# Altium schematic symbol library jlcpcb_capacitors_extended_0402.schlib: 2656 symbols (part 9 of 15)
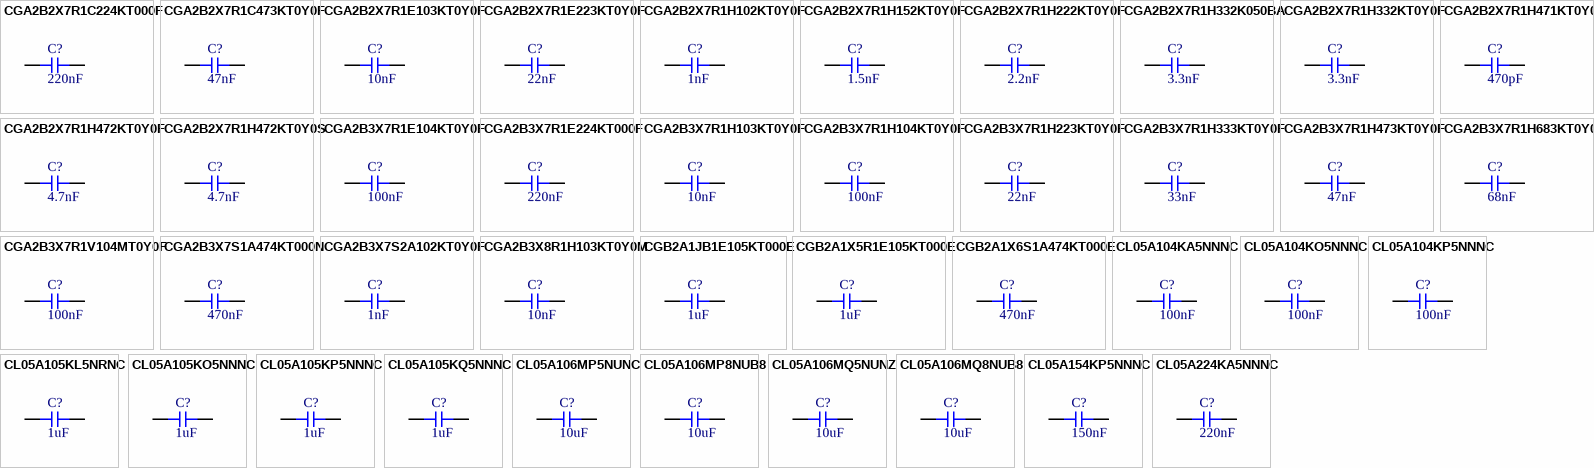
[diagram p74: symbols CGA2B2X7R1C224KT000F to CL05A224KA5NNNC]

## CL05A105KL5NRNC
designator C?  Capacitance: 1uF  (hidden comment: *)
Capacitor, Ceramic (MLCC), 1uF, ±10%, 35V, X5R, ±10%, SMD 0402; Manufacturer: Samsung Electro-Mechanics; Manufacturer Part Number: CL05A105KL5NRNC
footprint CAP-0402 (0402 (1005M) Capacitor)
pins: 1, 2

## CL05A105KO5NNNC
designator C?  Capacitance: 1uF  (hidden comment: *)
Capacitor, Ceramic (MLCC), 1uF, ±10%, 16V, X5R, ±10%, SMD 0402; Manufacturer: Samsung Electro-Mechanics; Manufacturer Part Number: CL05A105KO5NNNC
footprint CAP-0402 (0402 (1005M) Capacitor)
pins: 1, 2

## CL05A105KP5NNNC
designator C?  Capacitance: 1uF  (hidden comment: *)
Capacitor, Ceramic (MLCC), 1uF, ±10%, 10V, X5R, ±10%, SMD 0402; Manufacturer: Samsung Electro-Mechanics; Manufacturer Part Number: CL05A105KP5NNNC
footprint CAP-0402 (0402 (1005M) Capacitor)
pins: 1, 2

## CL05A105KQ5NNNC
designator C?  Capacitance: 1uF  (hidden comment: *)
Capacitor, Ceramic (MLCC), 1uF, ±10%, 6.3V, X5R, ±10%, SMD 0402; Manufacturer: Samsung Electro-Mechanics; Manufacturer Part Number: CL05A105KQ5NNNC
footprint CAP-0402 (0402 (1005M) Capacitor)
pins: 1, 2

## CL05A106MP5NUNC
designator C?  Capacitance: 10uF  (hidden comment: *)
Capacitor, Ceramic (MLCC), 10uF, ±20%, 10V, X5R, ±20%, SMD 0402; Manufacturer: Samsung Electro-Mechanics; Manufacturer Part Number: CL05A106MP5NUNC
footprint CAP-0402 (0402 (1005M) Capacitor)
pins: 1, 2

## CL05A106MP8NUB8
designator C?  Capacitance: 10uF  (hidden comment: *)
Capacitor, Ceramic (MLCC), 10uF, ±20%, 10V, X5R, ±20%, SMD 0402; Manufacturer: Samsung Electro-Mechanics; Manufacturer Part Number: CL05A106MP8NUB8
footprint CAP-0402 (0402 (1005M) Capacitor)
pins: 1, 2

## CL05A106MQ5NUNZ
designator C?  Capacitance: 10uF  (hidden comment: *)
Capacitor, Ceramic (MLCC), 10uF, ±20%, 6.3V, ±20%, SMD 0402; Manufacturer: Samsung Electro-Mechanics; Manufacturer Part Number: CL05A106MQ5NUNZ
footprint CAP-0402 (0402 (1005M) Capacitor)
pins: 1, 2

## CL05A106MQ8NUB8
designator C?  Capacitance: 10uF  (hidden comment: *)
Capacitor, Ceramic (MLCC), 10uF, ±20%, 6.3V, X5R, ±20%, SMD 0402; Manufacturer: Samsung Electro-Mechanics; Manufacturer Part Number: CL05A106MQ8NUB8
footprint CAP-0402 (0402 (1005M) Capacitor)
pins: 1, 2

## CL05A154KP5NNNC
designator C?  Capacitance: 150nF  (hidden comment: *)
Capacitor, Ceramic (MLCC), 150nF, ±10%, 10V, X5R, ±10%, SMD 0402; Manufacturer: Samsung Electro-Mechanics; Manufacturer Part Number: CL05A154KP5NNNC
footprint CAP-0402 (0402 (1005M) Capacitor)
pins: 1, 2

## CL05A224KA5NNNC
designator C?  Capacitance: 220nF  (hidden comment: *)
Capacitor, Ceramic (MLCC), 220nF, ±10%, 25V, X5R, ±10%, SMD 0402; Manufacturer: Samsung Electro-Mechanics; Manufacturer Part Number: CL05A224KA5NNNC
footprint CAP-0402 (0402 (1005M) Capacitor)
pins: 1, 2

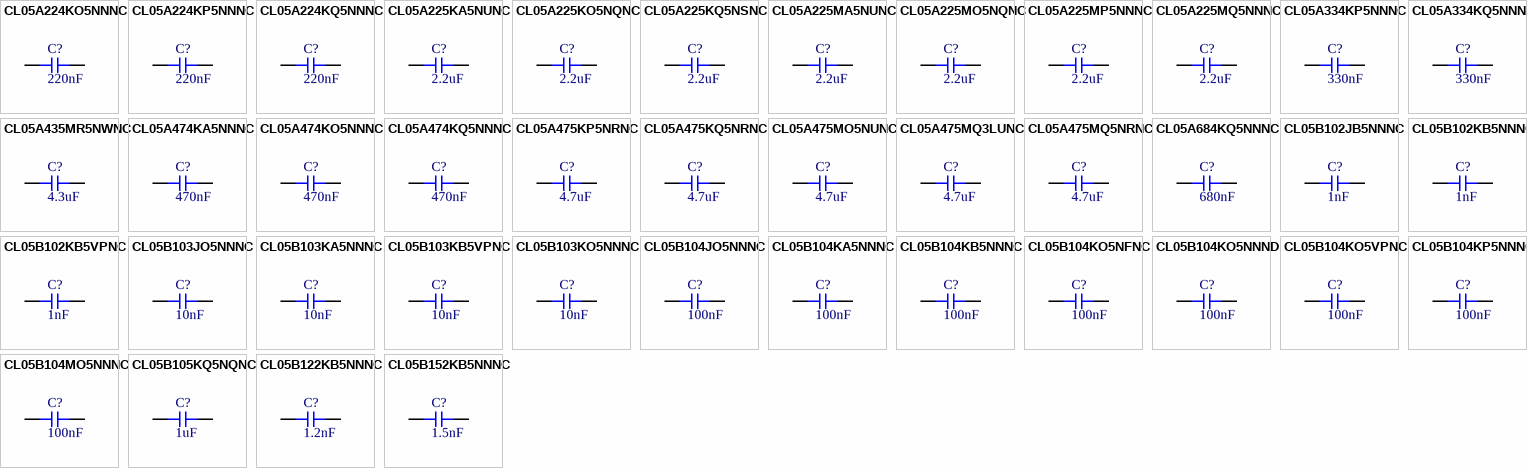
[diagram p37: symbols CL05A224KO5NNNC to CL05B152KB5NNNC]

## CL05A224KO5NNNC
designator C?  Capacitance: 220nF  (hidden comment: *)
Capacitor, Ceramic (MLCC), 220nF, ±10%, 16V, X5R, ±10%, SMD 0402; Manufacturer: Samsung Electro-Mechanics; Manufacturer Part Number: CL05A224KO5NNNC
footprint CAP-0402 (0402 (1005M) Capacitor)
pins: 1, 2

## CL05A224KP5NNNC
designator C?  Capacitance: 220nF  (hidden comment: *)
Capacitor, Ceramic (MLCC), 220nF, ±10%, 10V, X5R, ±10%, SMD 0402; Manufacturer: Samsung Electro-Mechanics; Manufacturer Part Number: CL05A224KP5NNNC
footprint CAP-0402 (0402 (1005M) Capacitor)
pins: 1, 2

## CL05A224KQ5NNNC
designator C?  Capacitance: 220nF  (hidden comment: *)
Capacitor, Ceramic (MLCC), 220nF, ±10%, 6.3V, X5R, ±10%, SMD 0402; Manufacturer: Samsung Electro-Mechanics; Manufacturer Part Number: CL05A224KQ5NNNC
footprint CAP-0402 (0402 (1005M) Capacitor)
pins: 1, 2

## CL05A225KA5NUNC
designator C?  Capacitance: 2.2uF  (hidden comment: *)
Capacitor, Ceramic (MLCC), 2.2uF, ±10%, 25V, X5R, ±10%, SMD 0402; Manufacturer: Samsung Electro-Mechanics; Manufacturer Part Number: CL05A225KA5NUNC
footprint CAP-0402 (0402 (1005M) Capacitor)
pins: 1, 2

## CL05A225KO5NQNC
designator C?  Capacitance: 2.2uF  (hidden comment: *)
Capacitor, Ceramic (MLCC), 2.2uF, ±10%, 16V, X5R, ±10%, SMD 0402; Manufacturer: Samsung Electro-Mechanics; Manufacturer Part Number: CL05A225KO5NQNC
footprint CAP-0402 (0402 (1005M) Capacitor)
pins: 1, 2

## CL05A225KQ5NSNC
designator C?  Capacitance: 2.2uF  (hidden comment: *)
Capacitor, Ceramic (MLCC), 2.2uF, ±10%, 6.3V, X5R, ±10%, SMD 0402; Manufacturer: Samsung Electro-Mechanics; Manufacturer Part Number: CL05A225KQ5NSNC
footprint CAP-0402 (0402 (1005M) Capacitor)
pins: 1, 2

## CL05A225MA5NUNC
designator C?  Capacitance: 2.2uF  (hidden comment: *)
Capacitor, Ceramic (MLCC), 2.2uF, ±20%, 25V, X5R, ±20%, SMD 0402; Manufacturer: Samsung Electro-Mechanics; Manufacturer Part Number: CL05A225MA5NUNC
footprint CAP-0402 (0402 (1005M) Capacitor)
pins: 1, 2

## CL05A225MO5NQNC
designator C?  Capacitance: 2.2uF  (hidden comment: *)
Capacitor, Ceramic (MLCC), 2.2uF, ±20%, 16V, X5R, ±20%, SMD 0402; Manufacturer: Samsung Electro-Mechanics; Manufacturer Part Number: CL05A225MO5NQNC
footprint CAP-0402 (0402 (1005M) Capacitor)
pins: 1, 2

## CL05A225MP5NNNC
designator C?  Capacitance: 2.2uF  (hidden comment: *)
Capacitor, Ceramic (MLCC), 2.2uF, ±20%, 10V, X5R, ±20%, SMD 0402; Manufacturer: Samsung Electro-Mechanics; Manufacturer Part Number: CL05A225MP5NNNC
footprint CAP-0402 (0402 (1005M) Capacitor)
pins: 1, 2

## CL05A225MQ5NNNC
designator C?  Capacitance: 2.2uF  (hidden comment: *)
Capacitor, Ceramic (MLCC), 2.2uF, ±20%, 6.3V, X5R, ±20%, SMD 0402; Manufacturer: Samsung Electro-Mechanics; Manufacturer Part Number: CL05A225MQ5NNNC
footprint CAP-0402 (0402 (1005M) Capacitor)
pins: 1, 2

## CL05A334KP5NNNC
designator C?  Capacitance: 330nF  (hidden comment: *)
Capacitor, Ceramic (MLCC), 330nF, ±10%, 10V, X5R, ±10%, SMD 0402; Manufacturer: Samsung Electro-Mechanics; Manufacturer Part Number: CL05A334KP5NNNC
footprint CAP-0402 (0402 (1005M) Capacitor)
pins: 1, 2

## CL05A334KQ5NNNC
designator C?  Capacitance: 330nF  (hidden comment: *)
Capacitor, Ceramic (MLCC), 330nF, ±10%, 6.3V, X5R, ±10%, SMD 0402; Manufacturer: Samsung Electro-Mechanics; Manufacturer Part Number: CL05A334KQ5NNNC
footprint CAP-0402 (0402 (1005M) Capacitor)
pins: 1, 2

## CL05A435MR5NWNC
designator C?  Capacitance: 4.3uF  (hidden comment: *)
Capacitor, Ceramic (MLCC), 4.3uF, ±20%, 4V, X5R, ±20%, SMD 0402; Manufacturer: Samsung Electro-Mechanics; Manufacturer Part Number: CL05A435MR5NWNC
footprint CAP-0402 (0402 (1005M) Capacitor)
pins: 1, 2

## CL05A474KA5NNNC
designator C?  Capacitance: 470nF  (hidden comment: *)
Capacitor, Ceramic (MLCC), 470nF, ±10%, 25V, X5R, ±10%, SMD 0402; Manufacturer: Samsung Electro-Mechanics; Manufacturer Part Number: CL05A474KA5NNNC
footprint CAP-0402 (0402 (1005M) Capacitor)
pins: 1, 2

## CL05A474KO5NNNC
designator C?  Capacitance: 470nF  (hidden comment: *)
Capacitor, Ceramic (MLCC), 470nF, ±10%, 16V, X5R, ±10%, SMD 0402; Manufacturer: Samsung Electro-Mechanics; Manufacturer Part Number: CL05A474KO5NNNC
footprint CAP-0402 (0402 (1005M) Capacitor)
pins: 1, 2

## CL05A474KQ5NNNC
designator C?  Capacitance: 470nF  (hidden comment: *)
Capacitor, Ceramic (MLCC), 470nF, ±10%, 6.3V, X5R, ±10%, SMD 0402; Manufacturer: Samsung Electro-Mechanics; Manufacturer Part Number: CL05A474KQ5NNNC
footprint CAP-0402 (0402 (1005M) Capacitor)
pins: 1, 2

## CL05A475KP5NRNC
designator C?  Capacitance: 4.7uF  (hidden comment: *)
Capacitor, Ceramic (MLCC), 4.7uF, ±10%, 10V, X5R, ±10%, SMD 0402; Manufacturer: Samsung Electro-Mechanics; Manufacturer Part Number: CL05A475KP5NRNC
footprint CAP-0402 (0402 (1005M) Capacitor)
pins: 1, 2

## CL05A475KQ5NRNC
designator C?  Capacitance: 4.7uF  (hidden comment: *)
Capacitor, Ceramic (MLCC), 4.7uF, ±10%, 6.3V, X5R, ±10%, SMD 0402; Manufacturer: Samsung Electro-Mechanics; Manufacturer Part Number: CL05A475KQ5NRNC
footprint CAP-0402 (0402 (1005M) Capacitor)
pins: 1, 2

## CL05A475MO5NUNC
designator C?  Capacitance: 4.7uF  (hidden comment: *)
Capacitor, Ceramic (MLCC), 4.7uF, ±20%, 16V, X5R, ±20%, SMD 0402; Manufacturer: Samsung Electro-Mechanics; Manufacturer Part Number: CL05A475MO5NUNC
footprint CAP-0402 (0402 (1005M) Capacitor)
pins: 1, 2

## CL05A475MQ3LUNC
designator C?  Capacitance: 4.7uF  (hidden comment: *)
Capacitor, Ceramic (MLCC), 4.7uF, ±20%, 6.3V, X5R, ±20%, SMD 0402; Manufacturer: Samsung Electro-Mechanics; Manufacturer Part Number: CL05A475MQ3LUNC
footprint CAP-0402 (0402 (1005M) Capacitor)
pins: 1, 2

## CL05A475MQ5NRNC
designator C?  Capacitance: 4.7uF  (hidden comment: *)
Capacitor, Ceramic (MLCC), 4.7uF, ±20%, 6.3V, X5R, ±20%, SMD 0402; Manufacturer: Samsung Electro-Mechanics; Manufacturer Part Number: CL05A475MQ5NRNC
footprint CAP-0402 (0402 (1005M) Capacitor)
pins: 1, 2

## CL05A684KQ5NNNC
designator C?  Capacitance: 680nF  (hidden comment: *)
Capacitor, Ceramic (MLCC), 680nF, ±10%, 6.3V, X5R, ±10%, SMD 0402; Manufacturer: Samsung Electro-Mechanics; Manufacturer Part Number: CL05A684KQ5NNNC
footprint CAP-0402 (0402 (1005M) Capacitor)
pins: 1, 2

## CL05B102JB5NNNC
designator C?  Capacitance: 1nF  (hidden comment: *)
Capacitor, Ceramic (MLCC), 1nF, ±5%, 50V, X7R, ±5%, SMD 0402; Manufacturer: Samsung Electro-Mechanics; Manufacturer Part Number: CL05B102JB5NNNC
footprint CAP-0402 (0402 (1005M) Capacitor)
pins: 1, 2

## CL05B102KB5NNNC
designator C?  Capacitance: 1nF  (hidden comment: *)
Capacitor, Ceramic (MLCC), 1nF, ±10%, 50V, X7R, ±10%, SMD 0402; Manufacturer: Samsung Electro-Mechanics; Manufacturer Part Number: CL05B102KB5NNNC
footprint CAP-0402 (0402 (1005M) Capacitor)
pins: 1, 2

## CL05B102KB5VPNC
designator C?  Capacitance: 1nF  (hidden comment: *)
Capacitor, Ceramic (MLCC), 1nF, ±10%, 50V, X7R, ±10%, SMD 0402; Manufacturer: Samsung Electro-Mechanics; Manufacturer Part Number: CL05B102KB5VPNC
footprint CAP-0402 (0402 (1005M) Capacitor)
pins: 1, 2

## CL05B103JO5NNNC
designator C?  Capacitance: 10nF  (hidden comment: *)
Capacitor, Ceramic (MLCC), 10nF, ±5%, 16V, X7R, ±5%, SMD 0402; Manufacturer: Samsung Electro-Mechanics; Manufacturer Part Number: CL05B103JO5NNNC
footprint CAP-0402 (0402 (1005M) Capacitor)
pins: 1, 2

## CL05B103KA5NNNC
designator C?  Capacitance: 10nF  (hidden comment: *)
Capacitor, Ceramic (MLCC), 10nF, ±10%, 25V, X7R, ±10%, SMD 0402; Manufacturer: Samsung Electro-Mechanics; Manufacturer Part Number: CL05B103KA5NNNC
footprint CAP-0402 (0402 (1005M) Capacitor)
pins: 1, 2

## CL05B103KB5VPNC
designator C?  Capacitance: 10nF  (hidden comment: *)
Capacitor, Ceramic (MLCC), 10nF, ±10%, 50V, X7R, ±10%, SMD 0402; Manufacturer: Samsung Electro-Mechanics; Manufacturer Part Number: CL05B103KB5VPNC
footprint CAP-0402 (0402 (1005M) Capacitor)
pins: 1, 2

## CL05B103KO5NNNC
designator C?  Capacitance: 10nF  (hidden comment: *)
Capacitor, Ceramic (MLCC), 10nF, ±10%, 16V, X7R, ±10%, SMD 0402; Manufacturer: Samsung Electro-Mechanics; Manufacturer Part Number: CL05B103KO5NNNC
footprint CAP-0402 (0402 (1005M) Capacitor)
pins: 1, 2

## CL05B104JO5NNNC
designator C?  Capacitance: 100nF  (hidden comment: *)
Capacitor, Ceramic (MLCC), 100nF, ±5%, 16V, ±5%, SMD 0402; Manufacturer: Samsung Electro-Mechanics; Manufacturer Part Number: CL05B104JO5NNNC
footprint CAP-0402 (0402 (1005M) Capacitor)
pins: 1, 2

## CL05B104KA5NNNC
designator C?  Capacitance: 100nF  (hidden comment: *)
Capacitor, Ceramic (MLCC), 100nF, ±10%, 25V, X7R, ±10%, SMD 0402; Manufacturer: Samsung Electro-Mechanics; Manufacturer Part Number: CL05B104KA5NNNC
footprint CAP-0402 (0402 (1005M) Capacitor)
pins: 1, 2

## CL05B104KB5NNNC
designator C?  Capacitance: 100nF  (hidden comment: *)
Capacitor, Ceramic (MLCC), 100nF, ±10%, 50V, ±10%, SMD 0402; Manufacturer: Samsung Electro-Mechanics; Manufacturer Part Number: CL05B104KB5NNNC
footprint CAP-0402 (0402 (1005M) Capacitor)
pins: 1, 2

## CL05B104KO5NFNC
designator C?  Capacitance: 100nF  (hidden comment: *)
Capacitor, Ceramic (MLCC), 100nF, ±10%, 16V, X7R, ±10%, SMD 0402; Manufacturer: Samsung Electro-Mechanics; Manufacturer Part Number: CL05B104KO5NFNC
footprint CAP-0402 (0402 (1005M) Capacitor)
pins: 1, 2

## CL05B104KO5NNND
designator C?  Capacitance: 100nF  (hidden comment: *)
Capacitor, Ceramic (MLCC), 100nF, ±10%, 16V, X7R, ±10%, SMD 0402; Manufacturer: Samsung Electro-Mechanics; Manufacturer Part Number: CL05B104KO5NNND
footprint CAP-0402 (0402 (1005M) Capacitor)
pins: 1, 2

## CL05B104KO5VPNC
designator C?  Capacitance: 100nF  (hidden comment: *)
Capacitor, Ceramic (MLCC), 100nF, ±10%, 16V, X7R, ±10%, SMD 0402; Manufacturer: Samsung Electro-Mechanics; Manufacturer Part Number: CL05B104KO5VPNC
footprint CAP-0402 (0402 (1005M) Capacitor)
pins: 1, 2

## CL05B104KP5NNNC
designator C?  Capacitance: 100nF  (hidden comment: *)
Capacitor, Ceramic (MLCC), 100nF, ±10%, 10V, X7R, ±10%, SMD 0402; Manufacturer: Samsung Electro-Mechanics; Manufacturer Part Number: CL05B104KP5NNNC
footprint CAP-0402 (0402 (1005M) Capacitor)
pins: 1, 2

## CL05B104MO5NNNC
designator C?  Capacitance: 100nF  (hidden comment: *)
Capacitor, Ceramic (MLCC), 100nF, ±20%, 16V, X7R, ±20%, SMD 0402; Manufacturer: Samsung Electro-Mechanics; Manufacturer Part Number: CL05B104MO5NNNC
footprint CAP-0402 (0402 (1005M) Capacitor)
pins: 1, 2

## CL05B105KQ5NQNC
designator C?  Capacitance: 1uF  (hidden comment: *)
Capacitor, Ceramic (MLCC), 1uF, ±10%, 6.3V, X7R, ±10%, SMD 0402; Manufacturer: Samsung Electro-Mechanics; Manufacturer Part Number: CL05B105KQ5NQNC
footprint CAP-0402 (0402 (1005M) Capacitor)
pins: 1, 2

## CL05B122KB5NNNC
designator C?  Capacitance: 1.2nF  (hidden comment: *)
Capacitor, Ceramic (MLCC), 1.2nF, ±10%, 50V, X7R, ±10%, SMD 0402; Manufacturer: Samsung Electro-Mechanics; Manufacturer Part Number: CL05B122KB5NNNC
footprint CAP-0402 (0402 (1005M) Capacitor)
pins: 1, 2

## CL05B152KB5NNNC
designator C?  Capacitance: 1.5nF  (hidden comment: *)
Capacitor, Ceramic (MLCC), 1.5nF, ±10%, 50V, X7R, ±10%, SMD 0402; Manufacturer: Samsung Electro-Mechanics; Manufacturer Part Number: CL05B152KB5NNNC
footprint CAP-0402 (0402 (1005M) Capacitor)
pins: 1, 2

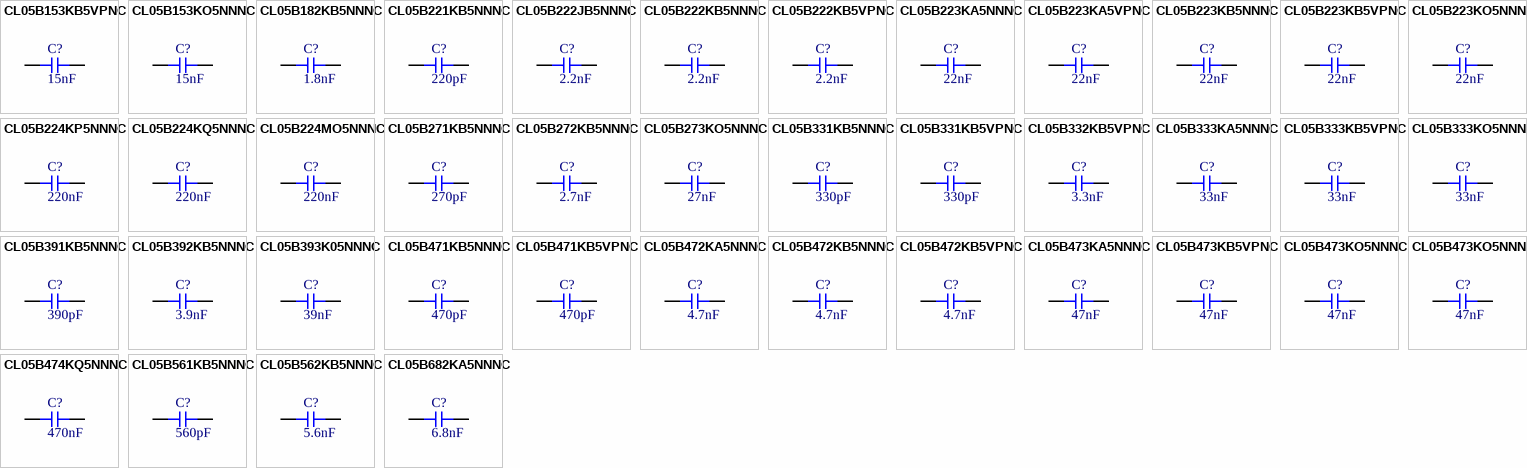
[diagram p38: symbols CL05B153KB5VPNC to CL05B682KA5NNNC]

## CL05B153KB5VPNC
designator C?  Capacitance: 15nF  (hidden comment: *)
Capacitor, Ceramic (MLCC), 15nF, ±10%, 50V, X7R, ±10%, SMD 0402; Manufacturer: Samsung Electro-Mechanics; Manufacturer Part Number: CL05B153KB5VPNC
footprint CAP-0402 (0402 (1005M) Capacitor)
pins: 1, 2

## CL05B153KO5NNNC
designator C?  Capacitance: 15nF  (hidden comment: *)
Capacitor, Ceramic (MLCC), 15nF, ±10%, 16V, X7R, ±10%, SMD 0402; Manufacturer: Samsung Electro-Mechanics; Manufacturer Part Number: CL05B153KO5NNNC
footprint CAP-0402 (0402 (1005M) Capacitor)
pins: 1, 2

## CL05B182KB5NNNC
designator C?  Capacitance: 1.8nF  (hidden comment: *)
Capacitor, Ceramic (MLCC), 1.8nF, ±10%, 50V, X7R, ±10%, SMD 0402; Manufacturer: Samsung Electro-Mechanics; Manufacturer Part Number: CL05B182KB5NNNC
footprint CAP-0402 (0402 (1005M) Capacitor)
pins: 1, 2

## CL05B221KB5NNNC
designator C?  Capacitance: 220pF  (hidden comment: *)
Capacitor, Ceramic (MLCC), 220pF, ±10%, 50V, X7R, ±10%, SMD 0402; Manufacturer: Samsung Electro-Mechanics; Manufacturer Part Number: CL05B221KB5NNNC
footprint CAP-0402 (0402 (1005M) Capacitor)
pins: 1, 2

## CL05B222JB5NNNC
designator C?  Capacitance: 2.2nF  (hidden comment: *)
Capacitor, Ceramic (MLCC), 2.2nF, ±5%, 50V, X7R, ±5%, SMD 0402; Manufacturer: Samsung Electro-Mechanics; Manufacturer Part Number: CL05B222JB5NNNC
footprint CAP-0402 (0402 (1005M) Capacitor)
pins: 1, 2

## CL05B222KB5NNNC
designator C?  Capacitance: 2.2nF  (hidden comment: *)
Capacitor, Ceramic (MLCC), 2.2nF, ±10%, 50V, X7R, ±10%, SMD 0402; Manufacturer: Samsung Electro-Mechanics; Manufacturer Part Number: CL05B222KB5NNNC
footprint CAP-0402 (0402 (1005M) Capacitor)
pins: 1, 2

## CL05B222KB5VPNC
designator C?  Capacitance: 2.2nF  (hidden comment: *)
Capacitor, Ceramic (MLCC), 2.2nF, ±10%, 50V, X7R, ±10%, SMD 0402; Manufacturer: Samsung Electro-Mechanics; Manufacturer Part Number: CL05B222KB5VPNC
footprint CAP-0402 (0402 (1005M) Capacitor)
pins: 1, 2

## CL05B223KA5NNNC
designator C?  Capacitance: 22nF  (hidden comment: *)
Capacitor, Ceramic (MLCC), 22nF, ±10%, 25V, X7R, ±10%, SMD 0402; Manufacturer: Samsung Electro-Mechanics; Manufacturer Part Number: CL05B223KA5NNNC
footprint CAP-0402 (0402 (1005M) Capacitor)
pins: 1, 2

## CL05B223KA5VPNC
designator C?  Capacitance: 22nF  (hidden comment: *)
Capacitor, Ceramic (MLCC), 22nF, ±10%, 25V, X7R, ±10%, SMD 0402; Manufacturer: Samsung Electro-Mechanics; Manufacturer Part Number: CL05B223KA5VPNC
footprint CAP-0402 (0402 (1005M) Capacitor)
pins: 1, 2

## CL05B223KB5NNNC
designator C?  Capacitance: 22nF  (hidden comment: *)
Capacitor, Ceramic (MLCC), 22nF, ±10%, 50V, X7R, ±10%, SMD 0402; Manufacturer: Samsung Electro-Mechanics; Manufacturer Part Number: CL05B223KB5NNNC
footprint CAP-0402 (0402 (1005M) Capacitor)
pins: 1, 2

## CL05B223KB5VPNC
designator C?  Capacitance: 22nF  (hidden comment: *)
Capacitor, Ceramic (MLCC), 22nF, ±10%, 50V, X7R, ±10%, SMD 0402; Manufacturer: Samsung Electro-Mechanics; Manufacturer Part Number: CL05B223KB5VPNC
footprint CAP-0402 (0402 (1005M) Capacitor)
pins: 1, 2

## CL05B223KO5NNNC
designator C?  Capacitance: 22nF  (hidden comment: *)
Capacitor, Ceramic (MLCC), 22nF, ±10%, 16V, X7R, ±10%, SMD 0402; Manufacturer: Samsung Electro-Mechanics; Manufacturer Part Number: CL05B223KO5NNNC
footprint CAP-0402 (0402 (1005M) Capacitor)
pins: 1, 2

## CL05B224KP5NNNC
designator C?  Capacitance: 220nF  (hidden comment: *)
Capacitor, Ceramic (MLCC), 220nF, ±10%, 10V, X7R, ±10%, SMD 0402; Manufacturer: Samsung Electro-Mechanics; Manufacturer Part Number: CL05B224KP5NNNC
footprint CAP-0402 (0402 (1005M) Capacitor)
pins: 1, 2

## CL05B224KQ5NNNC
designator C?  Capacitance: 220nF  (hidden comment: *)
Capacitor, Ceramic (MLCC), 220nF, ±10%, 6.3V, X7R, ±10%, SMD 0402; Manufacturer: Samsung Electro-Mechanics; Manufacturer Part Number: CL05B224KQ5NNNC
footprint CAP-0402 (0402 (1005M) Capacitor)
pins: 1, 2

## CL05B224MO5NNNC
designator C?  Capacitance: 220nF  (hidden comment: *)
Capacitor, Ceramic (MLCC), 220nF, ±20%, 16V, X7R, ±20%, SMD 0402; Manufacturer: Samsung Electro-Mechanics; Manufacturer Part Number: CL05B224MO5NNNC
footprint CAP-0402 (0402 (1005M) Capacitor)
pins: 1, 2

## CL05B271KB5NNNC
designator C?  Capacitance: 270pF  (hidden comment: *)
Capacitor, Ceramic (MLCC), 270pF, ±10%, 50V, X7R, ±10%, SMD 0402; Manufacturer: Samsung Electro-Mechanics; Manufacturer Part Number: CL05B271KB5NNNC
footprint CAP-0402 (0402 (1005M) Capacitor)
pins: 1, 2

## CL05B272KB5NNNC
designator C?  Capacitance: 2.7nF  (hidden comment: *)
Capacitor, Ceramic (MLCC), 2.7nF, ±10%, 50V, X7R, ±10%, SMD 0402; Manufacturer: Samsung Electro-Mechanics; Manufacturer Part Number: CL05B272KB5NNNC
footprint CAP-0402 (0402 (1005M) Capacitor)
pins: 1, 2

## CL05B273KO5NNNC
designator C?  Capacitance: 27nF  (hidden comment: *)
Capacitor, Ceramic (MLCC), 27nF, ±10%, 16V, X7R, ±10%, SMD 0402; Manufacturer: Samsung Electro-Mechanics; Manufacturer Part Number: CL05B273KO5NNNC
footprint CAP-0402 (0402 (1005M) Capacitor)
pins: 1, 2

## CL05B331KB5NNNC
designator C?  Capacitance: 330pF  (hidden comment: *)
Capacitor, Ceramic (MLCC), 330pF, ±10%, 50V, X7R, ±10%, SMD 0402; Manufacturer: Samsung Electro-Mechanics; Manufacturer Part Number: CL05B331KB5NNNC
footprint CAP-0402 (0402 (1005M) Capacitor)
pins: 1, 2

## CL05B331KB5VPNC
designator C?  Capacitance: 330pF  (hidden comment: *)
Capacitor, Ceramic (MLCC), 330pF, ±10%, 50V, X7R, ±10%, SMD 0402; Manufacturer: Samsung Electro-Mechanics; Manufacturer Part Number: CL05B331KB5VPNC
footprint CAP-0402 (0402 (1005M) Capacitor)
pins: 1, 2

## CL05B332KB5VPNC
designator C?  Capacitance: 3.3nF  (hidden comment: *)
Capacitor, Ceramic (MLCC), 3.3nF, ±10%, 50V, X7R, ±10%, SMD 0402; Manufacturer: Samsung Electro-Mechanics; Manufacturer Part Number: CL05B332KB5VPNC
footprint CAP-0402 (0402 (1005M) Capacitor)
pins: 1, 2

## CL05B333KA5NNNC
designator C?  Capacitance: 33nF  (hidden comment: *)
Capacitor, Ceramic (MLCC), 33nF, ±10%, 25V, X7R, ±10%, SMD 0402; Manufacturer: Samsung Electro-Mechanics; Manufacturer Part Number: CL05B333KA5NNNC
footprint CAP-0402 (0402 (1005M) Capacitor)
pins: 1, 2

## CL05B333KB5VPNC
designator C?  Capacitance: 33nF  (hidden comment: *)
Capacitor, Ceramic (MLCC), 33nF, ±10%, 50V, X7R, ±10%, SMD 0402; Manufacturer: Samsung Electro-Mechanics; Manufacturer Part Number: CL05B333KB5VPNC
footprint CAP-0402 (0402 (1005M) Capacitor)
pins: 1, 2

## CL05B333KO5NNNC
designator C?  Capacitance: 33nF  (hidden comment: *)
Capacitor, Ceramic (MLCC), 33nF, ±10%, 16V, X7R, ±10%, SMD 0402; Manufacturer: Samsung Electro-Mechanics; Manufacturer Part Number: CL05B333KO5NNNC
footprint CAP-0402 (0402 (1005M) Capacitor)
pins: 1, 2

## CL05B391KB5NNNC
designator C?  Capacitance: 390pF  (hidden comment: *)
Capacitor, Ceramic (MLCC), 390pF, ±10%, 50V, X7R, ±10%, SMD 0402; Manufacturer: Samsung Electro-Mechanics; Manufacturer Part Number: CL05B391KB5NNNC
footprint CAP-0402 (0402 (1005M) Capacitor)
pins: 1, 2

## CL05B392KB5NNNC
designator C?  Capacitance: 3.9nF  (hidden comment: *)
Capacitor, Ceramic (MLCC), 3.9nF, ±10%, 50V, X7R, ±10%, SMD 0402; Manufacturer: Samsung Electro-Mechanics; Manufacturer Part Number: CL05B392KB5NNNC
footprint CAP-0402 (0402 (1005M) Capacitor)
pins: 1, 2

## CL05B393K05NNNC
designator C?  Capacitance: 39nF  (hidden comment: *)
Capacitor, Ceramic (MLCC), 39nF, ±10%, 16V, X7R, ±10%, SMD 0402; Manufacturer: Samsung Electro-Mechanics; Manufacturer Part Number: CL05B393K05NNNC
footprint CAP-0402 (0402 (1005M) Capacitor)
pins: 1, 2

## CL05B471KB5NNNC
designator C?  Capacitance: 470pF  (hidden comment: *)
Capacitor, Ceramic (MLCC), 470pF, ±10%, 50V, X7R, ±10%, SMD 0402; Manufacturer: Samsung Electro-Mechanics; Manufacturer Part Number: CL05B471KB5NNNC
footprint CAP-0402 (0402 (1005M) Capacitor)
pins: 1, 2

## CL05B471KB5VPNC
designator C?  Capacitance: 470pF  (hidden comment: *)
Capacitor, Ceramic (MLCC), 470pF, ±10%, 50V, X7R, ±10%, SMD 0402; Manufacturer: Samsung Electro-Mechanics; Manufacturer Part Number: CL05B471KB5VPNC
footprint CAP-0402 (0402 (1005M) Capacitor)
pins: 1, 2

## CL05B472KA5NNNC
designator C?  Capacitance: 4.7nF  (hidden comment: *)
Capacitor, Ceramic (MLCC), 4.7nF, ±10%, 25V, X7R, ±10%, SMD 0402; Manufacturer: Samsung Electro-Mechanics; Manufacturer Part Number: CL05B472KA5NNNC
footprint CAP-0402 (0402 (1005M) Capacitor)
pins: 1, 2

## CL05B472KB5NNNC
designator C?  Capacitance: 4.7nF  (hidden comment: *)
Capacitor, Ceramic (MLCC), 4.7nF, ±10%, 50V, X7R, ±10%, SMD 0402; Manufacturer: Samsung Electro-Mechanics; Manufacturer Part Number: CL05B472KB5NNNC
footprint CAP-0402 (0402 (1005M) Capacitor)
pins: 1, 2

## CL05B472KB5VPNC
designator C?  Capacitance: 4.7nF  (hidden comment: *)
Capacitor, Ceramic (MLCC), 4.7nF, ±10%, 50V, X7R, ±10%, SMD 0402; Manufacturer: Samsung Electro-Mechanics; Manufacturer Part Number: CL05B472KB5VPNC
footprint CAP-0402 (0402 (1005M) Capacitor)
pins: 1, 2

## CL05B473KA5NNNC
designator C?  Capacitance: 47nF  (hidden comment: *)
Capacitor, Ceramic (MLCC), 47nF, ±10%, 25V, X7R, ±10%, SMD 0402; Manufacturer: Samsung Electro-Mechanics; Manufacturer Part Number: CL05B473KA5NNNC
footprint CAP-0402 (0402 (1005M) Capacitor)
pins: 1, 2

## CL05B473KB5VPNC
designator C?  Capacitance: 47nF  (hidden comment: *)
Capacitor, Ceramic (MLCC), 47nF, ±10%, 50V, X7R, ±10%, SMD 0402; Manufacturer: Samsung Electro-Mechanics; Manufacturer Part Number: CL05B473KB5VPNC
footprint CAP-0402 (0402 (1005M) Capacitor)
pins: 1, 2

## CL05B473KO5NNNC
designator C?  Capacitance: 47nF  (hidden comment: *)
Capacitor, Ceramic (MLCC), 47nF, ±10%, 16V, X7R, ±10%, SMD 0402; Manufacturer: Samsung Electro-Mechanics; Manufacturer Part Number: CL05B473KO5NNNC
footprint CAP-0402 (0402 (1005M) Capacitor)
pins: 1, 2

## CL05B473KO5NNND
designator C?  Capacitance: 47nF  (hidden comment: *)
Capacitor, Ceramic (MLCC), 47nF, ±10%, 16V, X7R, ±10%, SMD 0402; Manufacturer: Samsung Electro-Mechanics; Manufacturer Part Number: CL05B473KO5NNND
footprint CAP-0402 (0402 (1005M) Capacitor)
pins: 1, 2

## CL05B474KQ5NNNC
designator C?  Capacitance: 470nF  (hidden comment: *)
Capacitor, Ceramic (MLCC), 470nF, ±10%, 6.3V, X7R, ±10%, SMD 0402; Manufacturer: Samsung Electro-Mechanics; Manufacturer Part Number: CL05B474KQ5NNNC
footprint CAP-0402 (0402 (1005M) Capacitor)
pins: 1, 2

## CL05B561KB5NNNC
designator C?  Capacitance: 560pF  (hidden comment: *)
Capacitor, Ceramic (MLCC), 560pF, ±10%, 50V, X7R, ±10%, SMD 0402; Manufacturer: Samsung Electro-Mechanics; Manufacturer Part Number: CL05B561KB5NNNC
footprint CAP-0402 (0402 (1005M) Capacitor)
pins: 1, 2

## CL05B562KB5NNNC
designator C?  Capacitance: 5.6nF  (hidden comment: *)
Capacitor, Ceramic (MLCC), 5.6nF, ±10%, 50V, X7R, ±10%, SMD 0402; Manufacturer: Samsung Electro-Mechanics; Manufacturer Part Number: CL05B562KB5NNNC
footprint CAP-0402 (0402 (1005M) Capacitor)
pins: 1, 2

## CL05B682KA5NNNC
designator C?  Capacitance: 6.8nF  (hidden comment: *)
Capacitor, Ceramic (MLCC), 6.8nF, ±10%, 25V, X7R, ±10%, SMD 0402; Manufacturer: Samsung Electro-Mechanics; Manufacturer Part Number: CL05B682KA5NNNC
footprint CAP-0402 (0402 (1005M) Capacitor)
pins: 1, 2

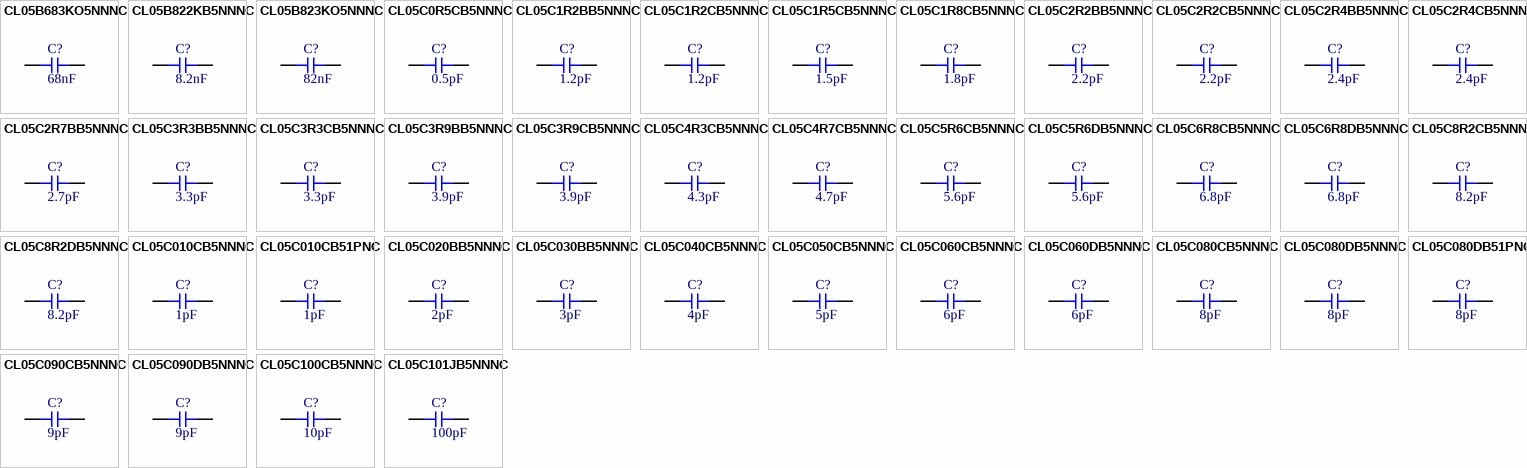
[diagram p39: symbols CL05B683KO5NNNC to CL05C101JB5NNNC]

## CL05B683KO5NNNC
designator C?  Capacitance: 68nF  (hidden comment: *)
Capacitor, Ceramic (MLCC), 68nF, ±10%, 16V, X7R, ±10%, SMD 0402; Manufacturer: Samsung Electro-Mechanics; Manufacturer Part Number: CL05B683KO5NNNC
footprint CAP-0402 (0402 (1005M) Capacitor)
pins: 1, 2

## CL05B822KB5NNNC
designator C?  Capacitance: 8.2nF  (hidden comment: *)
Capacitor, Ceramic (MLCC), 8.2nF, ±10%, 50V, X7R, ±10%, SMD 0402; Manufacturer: Samsung Electro-Mechanics; Manufacturer Part Number: CL05B822KB5NNNC
footprint CAP-0402 (0402 (1005M) Capacitor)
pins: 1, 2

## CL05B823KO5NNNC
designator C?  Capacitance: 82nF  (hidden comment: *)
Capacitor, Ceramic (MLCC), 82nF, ±10%, 16V, X7R, ±10%, SMD 0402; Manufacturer: Samsung Electro-Mechanics; Manufacturer Part Number: CL05B823KO5NNNC
footprint CAP-0402 (0402 (1005M) Capacitor)
pins: 1, 2

## CL05C0R5CB5NNNC
designator C?  Capacitance: 0.5pF  (hidden comment: *)
Capacitor, Ceramic (MLCC), 0.5pF, ±0.25pF, 50V, C0G, ±0.25pF, SMD 0402; Manufacturer: Samsung Electro-Mechanics; Manufacturer Part Number: CL05C0R5CB5NNNC
footprint CAP-0402 (0402 (1005M) Capacitor)
pins: 1, 2

## CL05C1R2BB5NNNC
designator C?  Capacitance: 1.2pF  (hidden comment: *)
Capacitor, Ceramic (MLCC), 1.2pF, ±0.1pF, 50V, C0G, ±0.1pF, SMD 0402; Manufacturer: Samsung Electro-Mechanics; Manufacturer Part Number: CL05C1R2BB5NNNC
footprint CAP-0402 (0402 (1005M) Capacitor)
pins: 1, 2

## CL05C1R2CB5NNNC
designator C?  Capacitance: 1.2pF  (hidden comment: *)
Capacitor, Ceramic (MLCC), 1.2pF, ±0.25pF, 50V, C0G, ±0.25pF, SMD 0402; Manufacturer: Samsung Electro-Mechanics; Manufacturer Part Number: CL05C1R2CB5NNNC
footprint CAP-0402 (0402 (1005M) Capacitor)
pins: 1, 2

## CL05C1R5CB5NNNC
designator C?  Capacitance: 1.5pF  (hidden comment: *)
Capacitor, Ceramic (MLCC), 1.5pF, ±0.25pF, 50V, C0G, ±0.25pF, SMD 0402; Manufacturer: Samsung Electro-Mechanics; Manufacturer Part Number: CL05C1R5CB5NNNC
footprint CAP-0402 (0402 (1005M) Capacitor)
pins: 1, 2

## CL05C1R8CB5NNNC
designator C?  Capacitance: 1.8pF  (hidden comment: *)
Capacitor, Ceramic (MLCC), 1.8pF, ±0.25pF, 50V, C0G, ±0.25pF, SMD 0402; Manufacturer: Samsung Electro-Mechanics; Manufacturer Part Number: CL05C1R8CB5NNNC
footprint CAP-0402 (0402 (1005M) Capacitor)
pins: 1, 2

## CL05C2R2BB5NNNC
designator C?  Capacitance: 2.2pF  (hidden comment: *)
Capacitor, Ceramic (MLCC), 2.2pF, ±0.1pF, 50V, C0G, ±0.1pF, SMD 0402; Manufacturer: Samsung Electro-Mechanics; Manufacturer Part Number: CL05C2R2BB5NNNC
footprint CAP-0402 (0402 (1005M) Capacitor)
pins: 1, 2

## CL05C2R2CB5NNNC
designator C?  Capacitance: 2.2pF  (hidden comment: *)
Capacitor, Ceramic (MLCC), 2.2pF, ±0.25pF, 50V, C0G, ±0.25pF, SMD 0402; Manufacturer: Samsung Electro-Mechanics; Manufacturer Part Number: CL05C2R2CB5NNNC
footprint CAP-0402 (0402 (1005M) Capacitor)
pins: 1, 2

## CL05C2R4BB5NNNC
designator C?  Capacitance: 2.4pF  (hidden comment: *)
Capacitor, Ceramic (MLCC), 2.4pF, ±0.1pF, 50V, C0G, ±0.1pF, SMD 0402; Manufacturer: Samsung Electro-Mechanics; Manufacturer Part Number: CL05C2R4BB5NNNC
footprint CAP-0402 (0402 (1005M) Capacitor)
pins: 1, 2

## CL05C2R4CB5NNNC
designator C?  Capacitance: 2.4pF  (hidden comment: *)
Capacitor, Ceramic (MLCC), 2.4pF, ±0.25pF, 50V, C0G, ±0.25pF, SMD 0402; Manufacturer: Samsung Electro-Mechanics; Manufacturer Part Number: CL05C2R4CB5NNNC
footprint CAP-0402 (0402 (1005M) Capacitor)
pins: 1, 2

## CL05C2R7BB5NNNC
designator C?  Capacitance: 2.7pF  (hidden comment: *)
Capacitor, Ceramic (MLCC), 2.7pF, ±0.1pF, 50V, C0G, ±0.1pF, SMD 0402; Manufacturer: Samsung Electro-Mechanics; Manufacturer Part Number: CL05C2R7BB5NNNC
footprint CAP-0402 (0402 (1005M) Capacitor)
pins: 1, 2

## CL05C3R3BB5NNNC
designator C?  Capacitance: 3.3pF  (hidden comment: *)
Capacitor, Ceramic (MLCC), 3.3pF, ±0.1pF, 50V, C0G, ±0.1pF, SMD 0402; Manufacturer: Samsung Electro-Mechanics; Manufacturer Part Number: CL05C3R3BB5NNNC
footprint CAP-0402 (0402 (1005M) Capacitor)
pins: 1, 2

## CL05C3R3CB5NNNC
designator C?  Capacitance: 3.3pF  (hidden comment: *)
Capacitor, Ceramic (MLCC), 3.3pF, ±0.25pF, 50V, C0G, ±0.25pF, SMD 0402; Manufacturer: Samsung Electro-Mechanics; Manufacturer Part Number: CL05C3R3CB5NNNC
footprint CAP-0402 (0402 (1005M) Capacitor)
pins: 1, 2

## CL05C3R9BB5NNNC
designator C?  Capacitance: 3.9pF  (hidden comment: *)
Capacitor, Ceramic (MLCC), 3.9pF, ±0.1pF, 50V, C0G, ±0.1pF, SMD 0402; Manufacturer: Samsung Electro-Mechanics; Manufacturer Part Number: CL05C3R9BB5NNNC
footprint CAP-0402 (0402 (1005M) Capacitor)
pins: 1, 2

## CL05C3R9CB5NNNC
designator C?  Capacitance: 3.9pF  (hidden comment: *)
Capacitor, Ceramic (MLCC), 3.9pF, ±0.25pF, 50V, C0G, ±0.25pF, SMD 0402; Manufacturer: Samsung Electro-Mechanics; Manufacturer Part Number: CL05C3R9CB5NNNC
footprint CAP-0402 (0402 (1005M) Capacitor)
pins: 1, 2

## CL05C4R3CB5NNNC
designator C?  Capacitance: 4.3pF  (hidden comment: *)
Capacitor, Ceramic (MLCC), 4.3pF, ±0.25pF, 50V, C0G, ±0.25pF, SMD 0402; Manufacturer: Samsung Electro-Mechanics; Manufacturer Part Number: CL05C4R3CB5NNNC
footprint CAP-0402 (0402 (1005M) Capacitor)
pins: 1, 2

## CL05C4R7CB5NNNC
designator C?  Capacitance: 4.7pF  (hidden comment: *)
Capacitor, Ceramic (MLCC), 4.7pF, ±0.25pF, 50V, C0G, ±0.25pF, SMD 0402; Manufacturer: Samsung Electro-Mechanics; Manufacturer Part Number: CL05C4R7CB5NNNC
footprint CAP-0402 (0402 (1005M) Capacitor)
pins: 1, 2

## CL05C5R6CB5NNNC
designator C?  Capacitance: 5.6pF  (hidden comment: *)
Capacitor, Ceramic (MLCC), 5.6pF, ±0.25pF, 50V, C0G, ±0.25pF, SMD 0402; Manufacturer: Samsung Electro-Mechanics; Manufacturer Part Number: CL05C5R6CB5NNNC
footprint CAP-0402 (0402 (1005M) Capacitor)
pins: 1, 2

## CL05C5R6DB5NNNC
designator C?  Capacitance: 5.6pF  (hidden comment: *)
Capacitor, Ceramic (MLCC), 5.6pF, ±0.5pF, 50V, C0G, ±0.5pF, SMD 0402; Manufacturer: Samsung Electro-Mechanics; Manufacturer Part Number: CL05C5R6DB5NNNC
footprint CAP-0402 (0402 (1005M) Capacitor)
pins: 1, 2

## CL05C6R8CB5NNNC
designator C?  Capacitance: 6.8pF  (hidden comment: *)
Capacitor, Ceramic (MLCC), 6.8pF, ±0.25pF, 50V, C0G, ±0.25pF, SMD 0402; Manufacturer: Samsung Electro-Mechanics; Manufacturer Part Number: CL05C6R8CB5NNNC
footprint CAP-0402 (0402 (1005M) Capacitor)
pins: 1, 2

## CL05C6R8DB5NNNC
designator C?  Capacitance: 6.8pF  (hidden comment: *)
Capacitor, Ceramic (MLCC), 6.8pF, ±0.5pF, 50V, C0G, ±0.5pF, SMD 0402; Manufacturer: Samsung Electro-Mechanics; Manufacturer Part Number: CL05C6R8DB5NNNC
footprint CAP-0402 (0402 (1005M) Capacitor)
pins: 1, 2

## CL05C8R2CB5NNNC
designator C?  Capacitance: 8.2pF  (hidden comment: *)
Capacitor, Ceramic (MLCC), 8.2pF, ±0.25pF, 50V, C0G, ±0.25pF, SMD 0402; Manufacturer: Samsung Electro-Mechanics; Manufacturer Part Number: CL05C8R2CB5NNNC
footprint CAP-0402 (0402 (1005M) Capacitor)
pins: 1, 2

## CL05C8R2DB5NNNC
designator C?  Capacitance: 8.2pF  (hidden comment: *)
Capacitor, Ceramic (MLCC), 8.2pF, ±0.5pF, 50V, C0G, ±0.5pF, SMD 0402; Manufacturer: Samsung Electro-Mechanics; Manufacturer Part Number: CL05C8R2DB5NNNC
footprint CAP-0402 (0402 (1005M) Capacitor)
pins: 1, 2

## CL05C010CB5NNNC
designator C?  Capacitance: 1pF  (hidden comment: *)
Capacitor, Ceramic (MLCC), 1pF, ±0.25pF, 50V, C0G, ±0.25pF, SMD 0402; Manufacturer: Samsung Electro-Mechanics; Manufacturer Part Number: CL05C010CB5NNNC
footprint CAP-0402 (0402 (1005M) Capacitor)
pins: 1, 2

## CL05C010CB51PNC
designator C?  Capacitance: 1pF  (hidden comment: *)
Capacitor, Ceramic (MLCC), 1pF, ±0.25pF, 50V, C0G, ±0.25pF, SMD 0402; Manufacturer: Samsung Electro-Mechanics; Manufacturer Part Number: CL05C010CB51PNC
footprint CAP-0402 (0402 (1005M) Capacitor)
pins: 1, 2

## CL05C020BB5NNNC
designator C?  Capacitance: 2pF  (hidden comment: *)
Capacitor, Ceramic (MLCC), 2pF, ±0.1pF, 50V, C0G, ±0.1pF, SMD 0402; Manufacturer: Samsung Electro-Mechanics; Manufacturer Part Number: CL05C020BB5NNNC
footprint CAP-0402 (0402 (1005M) Capacitor)
pins: 1, 2

## CL05C030BB5NNNC
designator C?  Capacitance: 3pF  (hidden comment: *)
Capacitor, Ceramic (MLCC), 3pF, ±0.1pF, 50V, C0G, ±0.1pF, SMD 0402; Manufacturer: Samsung Electro-Mechanics; Manufacturer Part Number: CL05C030BB5NNNC
footprint CAP-0402 (0402 (1005M) Capacitor)
pins: 1, 2

## CL05C040CB5NNNC
designator C?  Capacitance: 4pF  (hidden comment: *)
Capacitor, Ceramic (MLCC), 4pF, ±0.25pF, 50V, C0G, ±0.25pF, SMD 0402; Manufacturer: Samsung Electro-Mechanics; Manufacturer Part Number: CL05C040CB5NNNC
footprint CAP-0402 (0402 (1005M) Capacitor)
pins: 1, 2

## CL05C050CB5NNNC
designator C?  Capacitance: 5pF  (hidden comment: *)
Capacitor, Ceramic (MLCC), 5pF, ±0.25pF, 50V, C0G, ±0.25pF, SMD 0402; Manufacturer: Samsung Electro-Mechanics; Manufacturer Part Number: CL05C050CB5NNNC
footprint CAP-0402 (0402 (1005M) Capacitor)
pins: 1, 2

## CL05C060CB5NNNC
designator C?  Capacitance: 6pF  (hidden comment: *)
Capacitor, Ceramic (MLCC), 6pF, ±0.25pF, 50V, C0G, ±0.25pF, SMD 0402; Manufacturer: Samsung Electro-Mechanics; Manufacturer Part Number: CL05C060CB5NNNC
footprint CAP-0402 (0402 (1005M) Capacitor)
pins: 1, 2

## CL05C060DB5NNNC
designator C?  Capacitance: 6pF  (hidden comment: *)
Capacitor, Ceramic (MLCC), 6pF, ±0.5pF, 50V, C0G, ±0.5pF, SMD 0402; Manufacturer: Samsung Electro-Mechanics; Manufacturer Part Number: CL05C060DB5NNNC
footprint CAP-0402 (0402 (1005M) Capacitor)
pins: 1, 2

## CL05C080CB5NNNC
designator C?  Capacitance: 8pF  (hidden comment: *)
Capacitor, Ceramic (MLCC), 8pF, ±0.25pF, 50V, C0G, ±0.25pF, SMD 0402; Manufacturer: Samsung Electro-Mechanics; Manufacturer Part Number: CL05C080CB5NNNC
footprint CAP-0402 (0402 (1005M) Capacitor)
pins: 1, 2

## CL05C080DB5NNNC
designator C?  Capacitance: 8pF  (hidden comment: *)
Capacitor, Ceramic (MLCC), 8pF, ±0.5pF, 50V, C0G, ±0.5pF, SMD 0402; Manufacturer: Samsung Electro-Mechanics; Manufacturer Part Number: CL05C080DB5NNNC
footprint CAP-0402 (0402 (1005M) Capacitor)
pins: 1, 2

## CL05C080DB51PNC
designator C?  Capacitance: 8pF  (hidden comment: *)
Capacitor, Ceramic (MLCC), 8pF, ±0.5pF, 50V, C0G, ±0.5pF, SMD 0402; Manufacturer: Samsung Electro-Mechanics; Manufacturer Part Number: CL05C080DB51PNC
footprint CAP-0402 (0402 (1005M) Capacitor)
pins: 1, 2

## CL05C090CB5NNNC
designator C?  Capacitance: 9pF  (hidden comment: *)
Capacitor, Ceramic (MLCC), 9pF, ±0.25pF, 50V, C0G, ±0.25pF, SMD 0402; Manufacturer: Samsung Electro-Mechanics; Manufacturer Part Number: CL05C090CB5NNNC
footprint CAP-0402 (0402 (1005M) Capacitor)
pins: 1, 2

## CL05C090DB5NNNC
designator C?  Capacitance: 9pF  (hidden comment: *)
Capacitor, Ceramic (MLCC), 9pF, ±0.5pF, 50V, C0G, ±0.5pF, SMD 0402; Manufacturer: Samsung Electro-Mechanics; Manufacturer Part Number: CL05C090DB5NNNC
footprint CAP-0402 (0402 (1005M) Capacitor)
pins: 1, 2

## CL05C100CB5NNNC
designator C?  Capacitance: 10pF  (hidden comment: *)
Capacitor, Ceramic (MLCC), 10pF, ±0.25pF, 50V, C0G, ±0.25pF, SMD 0402; Manufacturer: Samsung Electro-Mechanics; Manufacturer Part Number: CL05C100CB5NNNC
footprint CAP-0402 (0402 (1005M) Capacitor)
pins: 1, 2

## CL05C101JB5NNNC
designator C?  Capacitance: 100pF  (hidden comment: *)
Capacitor, Ceramic (MLCC), 100pF, ±5%, 50V, C0G, ±5%, SMD 0402; Manufacturer: Samsung Electro-Mechanics; Manufacturer Part Number: CL05C101JB5NNNC
footprint CAP-0402 (0402 (1005M) Capacitor)
pins: 1, 2

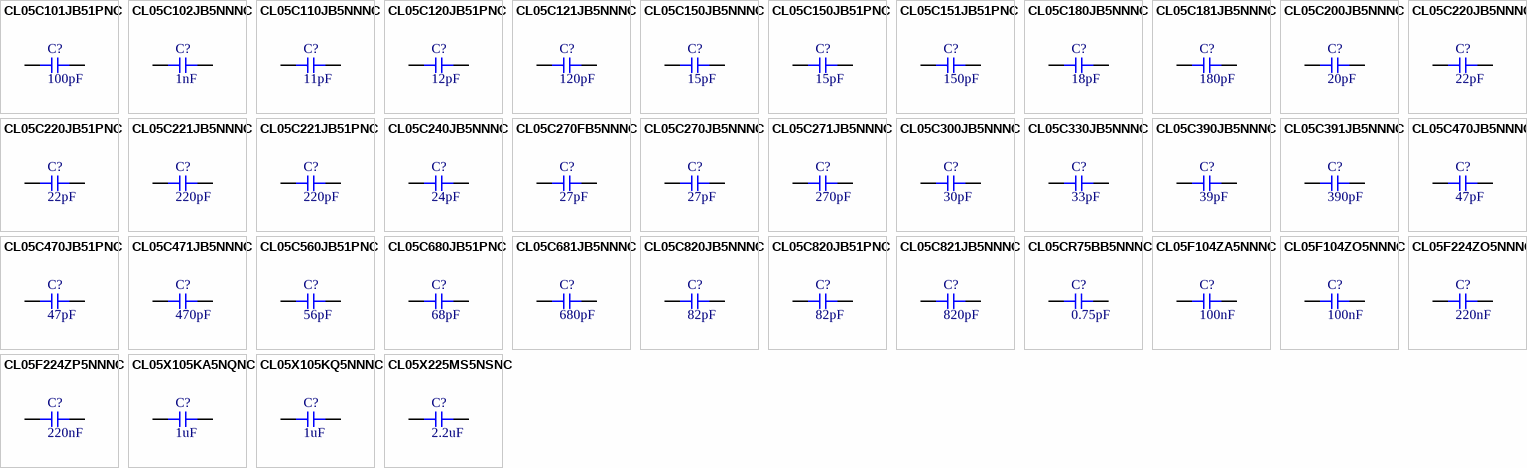
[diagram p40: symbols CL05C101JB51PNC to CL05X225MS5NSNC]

## CL05C101JB51PNC
designator C?  Capacitance: 100pF  (hidden comment: *)
Capacitor, Ceramic (MLCC), 100pF, ±5%, 50V, C0G, ±5%, SMD 0402; Manufacturer: Samsung Electro-Mechanics; Manufacturer Part Number: CL05C101JB51PNC
footprint CAP-0402 (0402 (1005M) Capacitor)
pins: 1, 2

## CL05C102JB5NNNC
designator C?  Capacitance: 1nF  (hidden comment: *)
Capacitor, Ceramic (MLCC), 1nF, ±5%, 50V, C0G, ±5%, SMD 0402; Manufacturer: Samsung Electro-Mechanics; Manufacturer Part Number: CL05C102JB5NNNC
footprint CAP-0402 (0402 (1005M) Capacitor)
pins: 1, 2

## CL05C110JB5NNNC
designator C?  Capacitance: 11pF  (hidden comment: *)
Capacitor, Ceramic (MLCC), 11pF, ±5%, 50V, C0G, ±5%, SMD 0402; Manufacturer: Samsung Electro-Mechanics; Manufacturer Part Number: CL05C110JB5NNNC
footprint CAP-0402 (0402 (1005M) Capacitor)
pins: 1, 2

## CL05C120JB51PNC
designator C?  Capacitance: 12pF  (hidden comment: *)
Capacitor, Ceramic (MLCC), 12pF, ±5%, 50V, C0G, ±5%, SMD 0402; Manufacturer: Samsung Electro-Mechanics; Manufacturer Part Number: CL05C120JB51PNC
footprint CAP-0402 (0402 (1005M) Capacitor)
pins: 1, 2

## CL05C121JB5NNNC
designator C?  Capacitance: 120pF  (hidden comment: *)
Capacitor, Ceramic (MLCC), 120pF, ±5%, 50V, C0G, ±5%, SMD 0402; Manufacturer: Samsung Electro-Mechanics; Manufacturer Part Number: CL05C121JB5NNNC
footprint CAP-0402 (0402 (1005M) Capacitor)
pins: 1, 2

## CL05C150JB5NNNC
designator C?  Capacitance: 15pF  (hidden comment: *)
Capacitor, Ceramic (MLCC), 15pF, ±5%, 50V, C0G, ±5%, SMD 0402; Manufacturer: Samsung Electro-Mechanics; Manufacturer Part Number: CL05C150JB5NNNC
footprint CAP-0402 (0402 (1005M) Capacitor)
pins: 1, 2

## CL05C150JB51PNC
designator C?  Capacitance: 15pF  (hidden comment: *)
Capacitor, Ceramic (MLCC), 15pF, ±5%, 50V, C0G, ±5%, SMD 0402; Manufacturer: Samsung Electro-Mechanics; Manufacturer Part Number: CL05C150JB51PNC
footprint CAP-0402 (0402 (1005M) Capacitor)
pins: 1, 2

## CL05C151JB51PNC
designator C?  Capacitance: 150pF  (hidden comment: *)
Capacitor, Ceramic (MLCC), 150pF, ±5%, 50V, C0G, ±5%, SMD 0402; Manufacturer: Samsung Electro-Mechanics; Manufacturer Part Number: CL05C151JB51PNC
footprint CAP-0402 (0402 (1005M) Capacitor)
pins: 1, 2

## CL05C180JB5NNNC
designator C?  Capacitance: 18pF  (hidden comment: *)
Capacitor, Ceramic (MLCC), 18pF, ±5%, 50V, C0G, ±5%, SMD 0402; Manufacturer: Samsung Electro-Mechanics; Manufacturer Part Number: CL05C180JB5NNNC
footprint CAP-0402 (0402 (1005M) Capacitor)
pins: 1, 2

## CL05C181JB5NNNC
designator C?  Capacitance: 180pF  (hidden comment: *)
Capacitor, Ceramic (MLCC), 180pF, ±5%, 50V, C0G, ±5%, SMD 0402; Manufacturer: Samsung Electro-Mechanics; Manufacturer Part Number: CL05C181JB5NNNC
footprint CAP-0402 (0402 (1005M) Capacitor)
pins: 1, 2

## CL05C200JB5NNNC
designator C?  Capacitance: 20pF  (hidden comment: *)
Capacitor, Ceramic (MLCC), 20pF, ±5%, 50V, C0G, ±5%, SMD 0402; Manufacturer: Samsung Electro-Mechanics; Manufacturer Part Number: CL05C200JB5NNNC
footprint CAP-0402 (0402 (1005M) Capacitor)
pins: 1, 2

## CL05C220JB5NNNC
designator C?  Capacitance: 22pF  (hidden comment: *)
Capacitor, Ceramic (MLCC), 22pF, ±5%, 50V, C0G, ±5%, SMD 0402; Manufacturer: Samsung Electro-Mechanics; Manufacturer Part Number: CL05C220JB5NNNC
footprint CAP-0402 (0402 (1005M) Capacitor)
pins: 1, 2

## CL05C220JB51PNC
designator C?  Capacitance: 22pF  (hidden comment: *)
Capacitor, Ceramic (MLCC), 22pF, ±5%, 50V, C0G, ±5%, SMD 0402; Manufacturer: Samsung Electro-Mechanics; Manufacturer Part Number: CL05C220JB51PNC
footprint CAP-0402 (0402 (1005M) Capacitor)
pins: 1, 2

## CL05C221JB5NNNC
designator C?  Capacitance: 220pF  (hidden comment: *)
Capacitor, Ceramic (MLCC), 220pF, ±5%, 50V, C0G, ±5%, SMD 0402; Manufacturer: Samsung Electro-Mechanics; Manufacturer Part Number: CL05C221JB5NNNC
footprint CAP-0402 (0402 (1005M) Capacitor)
pins: 1, 2

## CL05C221JB51PNC
designator C?  Capacitance: 220pF  (hidden comment: *)
Capacitor, Ceramic (MLCC), 220pF, ±5%, 50V, C0G, ±5%, SMD 0402; Manufacturer: Samsung Electro-Mechanics; Manufacturer Part Number: CL05C221JB51PNC
footprint CAP-0402 (0402 (1005M) Capacitor)
pins: 1, 2

## CL05C240JB5NNNC
designator C?  Capacitance: 24pF  (hidden comment: *)
Capacitor, Ceramic (MLCC), 24pF, ±5%, 50V, C0G, ±5%, SMD 0402; Manufacturer: Samsung Electro-Mechanics; Manufacturer Part Number: CL05C240JB5NNNC
footprint CAP-0402 (0402 (1005M) Capacitor)
pins: 1, 2

## CL05C270FB5NNNC
designator C?  Capacitance: 27pF  (hidden comment: *)
Capacitor, Ceramic (MLCC), 27pF, ±1pF, 50V, C0G, ±1pF, SMD 0402; Manufacturer: Samsung Electro-Mechanics; Manufacturer Part Number: CL05C270FB5NNNC
footprint CAP-0402 (0402 (1005M) Capacitor)
pins: 1, 2

## CL05C270JB5NNNC
designator C?  Capacitance: 27pF  (hidden comment: *)
Capacitor, Ceramic (MLCC), 27pF, ±5%, 50V, C0G, ±5%, SMD 0402; Manufacturer: Samsung Electro-Mechanics; Manufacturer Part Number: CL05C270JB5NNNC
footprint CAP-0402 (0402 (1005M) Capacitor)
pins: 1, 2

## CL05C271JB5NNNC
designator C?  Capacitance: 270pF  (hidden comment: *)
Capacitor, Ceramic (MLCC), 270pF, ±5%, 50V, C0G, ±5%, SMD 0402; Manufacturer: Samsung Electro-Mechanics; Manufacturer Part Number: CL05C271JB5NNNC
footprint CAP-0402 (0402 (1005M) Capacitor)
pins: 1, 2

## CL05C300JB5NNNC
designator C?  Capacitance: 30pF  (hidden comment: *)
Capacitor, Ceramic (MLCC), 30pF, ±5%, 50V, C0G, ±5%, SMD 0402; Manufacturer: Samsung Electro-Mechanics; Manufacturer Part Number: CL05C300JB5NNNC
footprint CAP-0402 (0402 (1005M) Capacitor)
pins: 1, 2

## CL05C330JB5NNNC
designator C?  Capacitance: 33pF  (hidden comment: *)
Capacitor, Ceramic (MLCC), 33pF, ±5%, 50V, C0G, ±5%, SMD 0402; Manufacturer: Samsung Electro-Mechanics; Manufacturer Part Number: CL05C330JB5NNNC
footprint CAP-0402 (0402 (1005M) Capacitor)
pins: 1, 2

## CL05C390JB5NNNC
designator C?  Capacitance: 39pF  (hidden comment: *)
Capacitor, Ceramic (MLCC), 39pF, ±5%, 50V, C0G, ±5%, SMD 0402; Manufacturer: Samsung Electro-Mechanics; Manufacturer Part Number: CL05C390JB5NNNC
footprint CAP-0402 (0402 (1005M) Capacitor)
pins: 1, 2

## CL05C391JB5NNNC
designator C?  Capacitance: 390pF  (hidden comment: *)
Capacitor, Ceramic (MLCC), 390pF, ±5%, 50V, C0G, ±5%, SMD 0402; Manufacturer: Samsung Electro-Mechanics; Manufacturer Part Number: CL05C391JB5NNNC
footprint CAP-0402 (0402 (1005M) Capacitor)
pins: 1, 2

## CL05C470JB5NNNC
designator C?  Capacitance: 47pF  (hidden comment: *)
Capacitor, Ceramic (MLCC), 47pF, ±5%, 50V, C0G, ±5%, SMD 0402; Manufacturer: Samsung Electro-Mechanics; Manufacturer Part Number: CL05C470JB5NNNC
footprint CAP-0402 (0402 (1005M) Capacitor)
pins: 1, 2

## CL05C470JB51PNC
designator C?  Capacitance: 47pF  (hidden comment: *)
Capacitor, Ceramic (MLCC), 47pF, ±5%, 50V, C0G, ±5%, SMD 0402; Manufacturer: Samsung Electro-Mechanics; Manufacturer Part Number: CL05C470JB51PNC
footprint CAP-0402 (0402 (1005M) Capacitor)
pins: 1, 2

## CL05C471JB5NNNC
designator C?  Capacitance: 470pF  (hidden comment: *)
Capacitor, Ceramic (MLCC), 470pF, ±5%, 50V, C0G, ±5%, SMD 0402; Manufacturer: Samsung Electro-Mechanics; Manufacturer Part Number: CL05C471JB5NNNC
footprint CAP-0402 (0402 (1005M) Capacitor)
pins: 1, 2

## CL05C560JB51PNC
designator C?  Capacitance: 56pF  (hidden comment: *)
Capacitor, Ceramic (MLCC), 56pF, ±5%, 50V, C0G, ±5%, SMD 0402; Manufacturer: Samsung Electro-Mechanics; Manufacturer Part Number: CL05C560JB51PNC
footprint CAP-0402 (0402 (1005M) Capacitor)
pins: 1, 2

## CL05C680JB51PNC
designator C?  Capacitance: 68pF  (hidden comment: *)
Capacitor, Ceramic (MLCC), 68pF, ±5%, 50V, C0G, ±5%, SMD 0402; Manufacturer: Samsung Electro-Mechanics; Manufacturer Part Number: CL05C680JB51PNC
footprint CAP-0402 (0402 (1005M) Capacitor)
pins: 1, 2

## CL05C681JB5NNNC
designator C?  Capacitance: 680pF  (hidden comment: *)
Capacitor, Ceramic (MLCC), 680pF, ±5%, 50V, C0G, ±5%, SMD 0402; Manufacturer: Samsung Electro-Mechanics; Manufacturer Part Number: CL05C681JB5NNNC
footprint CAP-0402 (0402 (1005M) Capacitor)
pins: 1, 2

## CL05C820JB5NNNC
designator C?  Capacitance: 82pF  (hidden comment: *)
Capacitor, Ceramic (MLCC), 82pF, ±5%, 50V, C0G, ±5%, SMD 0402; Manufacturer: Samsung Electro-Mechanics; Manufacturer Part Number: CL05C820JB5NNNC
footprint CAP-0402 (0402 (1005M) Capacitor)
pins: 1, 2

## CL05C820JB51PNC
designator C?  Capacitance: 82pF  (hidden comment: *)
Capacitor, Ceramic (MLCC), 82pF, ±5%, 50V, C0G, ±5%, SMD 0402; Manufacturer: Samsung Electro-Mechanics; Manufacturer Part Number: CL05C820JB51PNC
footprint CAP-0402 (0402 (1005M) Capacitor)
pins: 1, 2

## CL05C821JB5NNNC
designator C?  Capacitance: 820pF  (hidden comment: *)
Capacitor, Ceramic (MLCC), 820pF, ±5%, 50V, C0G, ±5%, SMD 0402; Manufacturer: Samsung Electro-Mechanics; Manufacturer Part Number: CL05C821JB5NNNC
footprint CAP-0402 (0402 (1005M) Capacitor)
pins: 1, 2

## CL05CR75BB5NNNC
designator C?  Capacitance: 0.75pF  (hidden comment: *)
Capacitor, Ceramic (MLCC), 0.75pF, ±0.1pF, 50V, C0G, ±0.1pF, SMD 0402; Manufacturer: Samsung Electro-Mechanics; Manufacturer Part Number: CL05CR75BB5NNNC
footprint CAP-0402 (0402 (1005M) Capacitor)
pins: 1, 2

## CL05F104ZA5NNNC
designator C?  Capacitance: 100nF  (hidden comment: *)
Capacitor, Ceramic (MLCC), 100nF, 25V, Y5V, SMD 0402; Manufacturer: Samsung Electro-Mechanics; Manufacturer Part Number: CL05F104ZA5NNNC; Temperature Rating: -20%~+80%
footprint CAP-0402 (0402 (1005M) Capacitor)
pins: 1, 2

## CL05F104ZO5NNNC
designator C?  Capacitance: 100nF  (hidden comment: *)
Capacitor, Ceramic (MLCC), 100nF, 16V, Y5V, SMD 0402; Manufacturer: Samsung Electro-Mechanics; Manufacturer Part Number: CL05F104ZO5NNNC; Temperature Rating: -20%~+80%
footprint CAP-0402 (0402 (1005M) Capacitor)
pins: 1, 2

## CL05F224ZO5NNNC
designator C?  Capacitance: 220nF  (hidden comment: *)
Capacitor, Ceramic (MLCC), 220nF, 16V, Y5V, SMD 0402; Manufacturer: Samsung Electro-Mechanics; Manufacturer Part Number: CL05F224ZO5NNNC; Temperature Rating: -20%~+80%
footprint CAP-0402 (0402 (1005M) Capacitor)
pins: 1, 2

## CL05F224ZP5NNNC
designator C?  Capacitance: 220nF  (hidden comment: *)
Capacitor, Ceramic (MLCC), 220nF, 10V, Y5V, SMD 0402; Manufacturer: Samsung Electro-Mechanics; Manufacturer Part Number: CL05F224ZP5NNNC; Temperature Rating: -20%~+80%
footprint CAP-0402 (0402 (1005M) Capacitor)
pins: 1, 2

## CL05X105KA5NQNC
designator C?  Capacitance: 1uF  (hidden comment: *)
Capacitor, Ceramic (MLCC), 1uF, ±10%, 25V, X6S, ±10%, SMD 0402; Manufacturer: Samsung Electro-Mechanics; Manufacturer Part Number: CL05X105KA5NQNC
footprint CAP-0402 (0402 (1005M) Capacitor)
pins: 1, 2

## CL05X105KQ5NNNC
designator C?  Capacitance: 1uF  (hidden comment: *)
Capacitor, Ceramic (MLCC), 1uF, ±10%, 6.3V, X6S, ±10%, SMD 0402; Manufacturer: Samsung Electro-Mechanics; Manufacturer Part Number: CL05X105KQ5NNNC
footprint CAP-0402 (0402 (1005M) Capacitor)
pins: 1, 2

## CL05X225MS5NSNC
designator C?  Capacitance: 2.2uF  (hidden comment: *)
Capacitor, Ceramic (MLCC), 2.2uF, ±20%, 2.5V, X6S, ±20%, SMD 0402; Manufacturer: Samsung Electro-Mechanics; Manufacturer Part Number: CL05X225MS5NSNC
footprint CAP-0402 (0402 (1005M) Capacitor)
pins: 1, 2

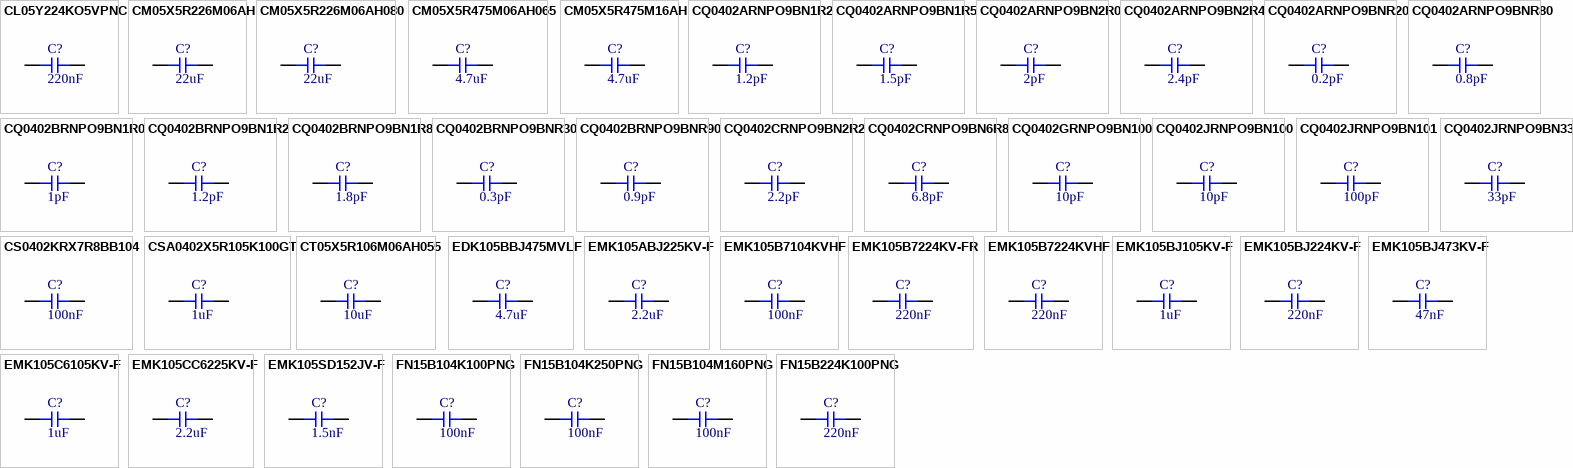
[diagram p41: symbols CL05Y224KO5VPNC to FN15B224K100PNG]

## CL05Y224KO5VPNC
designator C?  Capacitance: 220nF  (hidden comment: *)
Capacitor, Ceramic (MLCC), 220nF, ±10%, 16V, X7S, ±10%, SMD 0402; Manufacturer: Samsung Electro-Mechanics; Manufacturer Part Number: CL05Y224KO5VPNC
footprint CAP-0402 (0402 (1005M) Capacitor)
pins: 1, 2

## CM05X5R226M06AH
designator C?  Capacitance: 22uF  (hidden comment: *)
Capacitor, Ceramic (MLCC), 22uF, ±20%, 6.3V, ±20%, SMD 0402; Manufacturer: Kyocera; Manufacturer Part Number: CM05X5R226M06AH
footprint CAP-0402 (0402 (1005M) Capacitor)
pins: 1, 2

## CM05X5R226M06AH080
designator C?  Capacitance: 22uF  (hidden comment: *)
Capacitor, Ceramic (MLCC), 22uF, ±20%, 6.3V, X5R, ±20%, SMD 0402; Manufacturer: Kyocera; Manufacturer Part Number: CM05X5R226M06AH080
footprint CAP-0402 (0402 (1005M) Capacitor)
pins: 1, 2

## CM05X5R475M06AH065
designator C?  Capacitance: 4.7uF  (hidden comment: *)
Capacitor, Ceramic (MLCC), 4.7uF, ±20%, 6.3V, X5R, ±20%, SMD 0402; Manufacturer: Kyocera; Manufacturer Part Number: CM05X5R475M06AH065
footprint CAP-0402 (0402 (1005M) Capacitor)
pins: 1, 2

## CM05X5R475M16AH
designator C?  Capacitance: 4.7uF  (hidden comment: *)
Capacitor, Ceramic (MLCC), 4.7uF, ±20%, 16V, X5R, ±20%, SMD 0402; Manufacturer: Kyocera; Manufacturer Part Number: CM05X5R475M16AH
footprint CAP-0402 (0402 (1005M) Capacitor)
pins: 1, 2

## CQ0402ARNPO9BN1R2
designator C?  Capacitance: 1.2pF  (hidden comment: *)
Capacitor, Ceramic (MLCC), 1.2pF, ±0.05pF, 50V, NP0, ±0.05pF, SMD 0402; Manufacturer: YAGEO; Manufacturer Part Number: CQ0402ARNPO9BN1R2
footprint CAP-0402 (0402 (1005M) Capacitor)
pins: 1, 2

## CQ0402ARNPO9BN1R5
designator C?  Capacitance: 1.5pF  (hidden comment: *)
Capacitor, Ceramic (MLCC), 1.5pF, ±0.05pF, 50V, NP0, ±0.05pF, SMD 0402; Manufacturer: YAGEO; Manufacturer Part Number: CQ0402ARNPO9BN1R5
footprint CAP-0402 (0402 (1005M) Capacitor)
pins: 1, 2

## CQ0402ARNPO9BN2R0
designator C?  Capacitance: 2pF  (hidden comment: *)
Capacitor, Ceramic (MLCC), 2pF, ±0.05pF, 50V, NP0, ±0.05pF, SMD 0402; Manufacturer: YAGEO; Manufacturer Part Number: CQ0402ARNPO9BN2R0
footprint CAP-0402 (0402 (1005M) Capacitor)
pins: 1, 2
